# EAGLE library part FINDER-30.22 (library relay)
SUBMINIATURE DIL-RELAIS FINDER 30.22.9.024.0000 Kontakt max. AC - 125V Distributor: Farnell Bestell Nr.: 1217371 Source: http://www.farnell.com/datasheets/87634.pdf
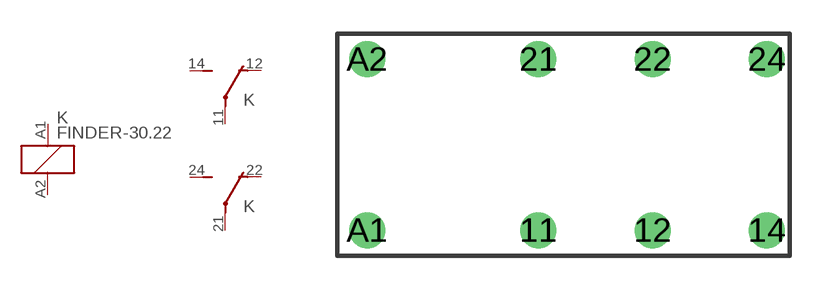
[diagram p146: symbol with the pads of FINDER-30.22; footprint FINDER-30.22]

Designator prefix K; gates K=K -1=U -2=U

## FINDER-30.22 (OC_FARNELL: unknown; OC_NEWARK: unknown)  [FINDER-30.22]
11  -1:P  pas
12  -1:O  pas
14  -1:S  pas
21  -2:P  pas
22  -2:O  pas
24  -2:S  pas
A1  K:1  pas
A2  K:2  pas

## Footprint FINDER-30.22 (pad centres in mm)
30 Series - Subminiature DIL relays 2 A Finder Source: http://www.farnell.com/datasheets/87634.pdf
drill 1 pad 1.6 round: 11 -1.27,-3.81; 12 3.81,-3.81; 14 8.89,-3.81; 21 -1.27,3.81; 22 3.81,3.81; 24 8.89,3.81; A1 -8.89,-3.81; A2 -8.89,3.81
